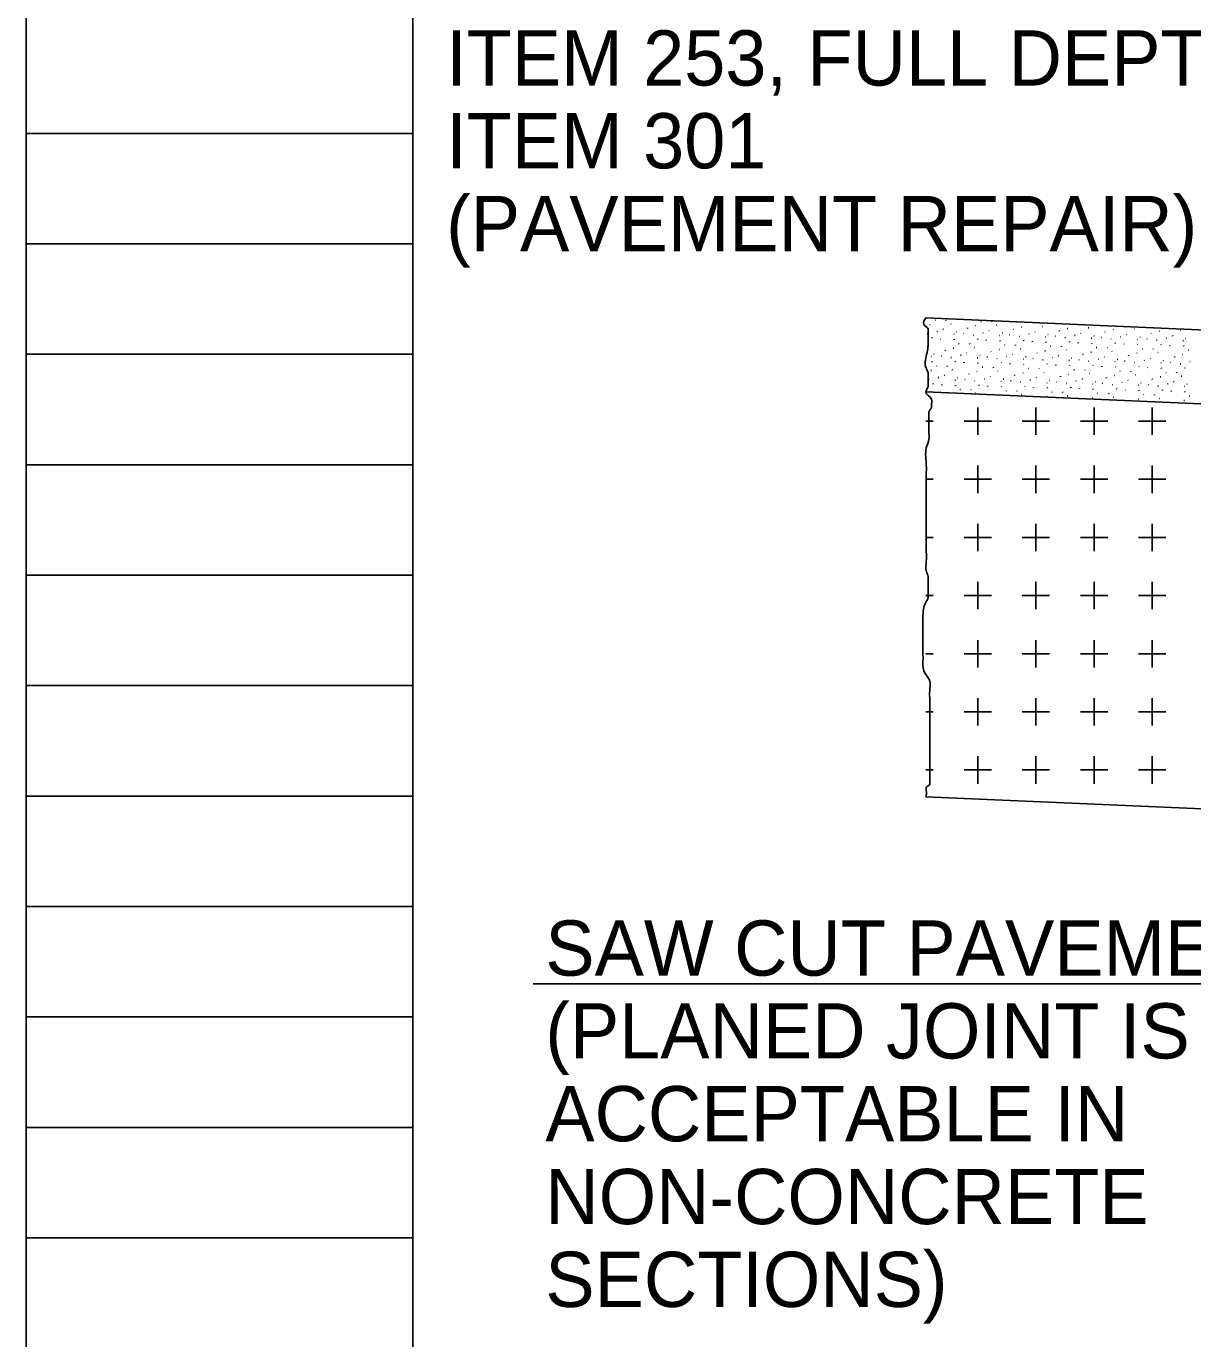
# Model space of a CAD drawing. Extents: x 0 to 34, y 0 to 22.
# Drawn here: x 16.76 to 19.716, y 10.524 to 13.852 of the extents above; entities that cross this region are included whole.
import ezdxf

# ---------------------------------------------------------------- set-up
doc = ezdxf.new("R2010")
doc.units = 0
doc.layers.add('Default', color=7, linetype='Continuous')
doc.layers.add('SH_Data', color=7, linetype='Continuous')

msp = doc.modelspace()

# ---------------------------------------------------------------- linework, layer by layer
at = {"layer": 'Default'}
for p, q in [((19.0496, 13.0955), (19.0506, 13.0951)), ((19.0633, 13.1068), (19.0645, 13.1066)), ((19.0681, 13.0776), (19.0691, 13.0775)), ((19.0833, 13.0835), (19.0845, 13.0826)), ((19.0915, 13.1056), (19.0908, 13.107)), ((19.1028, 13.0973), (19.104, 13.0971)), ((19.1458, 13.0856), (19.1453, 13.0871)), ((19.1658, 13.0921), (19.1668, 13.092)), ((19.1796, 13.1036), (19.1806, 13.1035)), ((19.1996, 13.0803), (19.2006, 13.0795)), ((19.2078, 13.1023), (19.2071, 13.1038)), ((19.2191, 13.094), (19.2201, 13.0938)), ((19.262, 13.0825), (19.2615, 13.0838)), ((19.2821, 13.089), (19.2831, 13.0886)), ((19.2958, 13.1003), (19.2968, 13.1001)), ((19.324, 13.0991), (19.3236, 13.1)), ((19.3353, 13.0908), (19.3365, 13.0906)), ((19.3783, 13.0791), (19.3778, 13.0806)), ((19.3983, 13.0856), (19.3995, 13.0855)), ((19.4516, 13.0875), (19.4526, 13.0873)), ((19.5146, 13.0825), (19.5156, 13.0821)), ((19.568, 13.0843), (19.569, 13.0841)), ((19.6308, 13.0791), (19.632, 13.079)), ((19.6841, 13.081), (19.6851, 13.0808)), ((19.0436, 13.0721), (19.0446, 13.0718)), ((19.0555, 13.0608), (19.0548, 13.0623)), ((19.0775, 13.0583), (19.077, 13.0596)), ((19.1105, 13.071), (19.1115, 13.0708)), ((19.112, 13.0568), (19.1115, 13.0581)), ((19.1166, 13.0768), (19.1178, 13.0765)), ((19.123, 13.0471), (19.1241, 13.0468)), ((19.1351, 13.0726), (19.1363, 13.0723)), ((19.1511, 13.0458), (19.1506, 13.0473)), ((19.1598, 13.0688), (19.161, 13.0686)), ((19.1718, 13.0576), (19.1711, 13.059)), ((19.1843, 13.0745), (19.1855, 13.0743)), ((19.1936, 13.055), (19.1931, 13.0563)), ((19.2266, 13.0676), (19.2278, 13.0675)), ((19.2283, 13.0535), (19.2278, 13.055)), ((19.233, 13.0735), (19.234, 13.0733)), ((19.2515, 13.0693), (19.2525, 13.0691)), ((19.2761, 13.0655), (19.2771, 13.0653)), ((19.288, 13.0543), (19.2875, 13.0558)), ((19.3006, 13.0711), (19.3016, 13.071)), ((19.31, 13.0518), (19.3093, 13.0531)), ((19.316, 13.077), (19.317, 13.0761)), ((19.343, 13.0643), (19.344, 13.0641)), ((19.3445, 13.0503), (19.344, 13.0516)), ((19.3491, 13.0703), (19.3503, 13.07)), ((19.3676, 13.066), (19.3686, 13.0658)), ((19.3925, 13.0623), (19.3935, 13.062)), ((19.4041, 13.0511), (19.4036, 13.0525)), ((19.4168, 13.068), (19.418, 13.0678)), ((19.4263, 13.0485), (19.4256, 13.0498)), ((19.4321, 13.0738), (19.4331, 13.073)), ((19.4591, 13.0611), (19.4603, 13.061)), ((19.4608, 13.047), (19.4603, 13.0485)), ((19.4655, 13.067), (19.4666, 13.0668)), ((19.484, 13.0628), (19.485, 13.0625)), ((19.4946, 13.076), (19.4941, 13.0773)), ((19.5086, 13.059), (19.5096, 13.0588)), ((19.5205, 13.0478), (19.52, 13.0493)), ((19.5331, 13.0646), (19.5343, 13.0645)), ((19.5425, 13.0453), (19.542, 13.0466)), ((19.5485, 13.0705), (19.5495, 13.0696)), ((19.5755, 13.0578), (19.5765, 13.0576)), ((19.5771, 13.0438), (19.5765, 13.0451)), ((19.5818, 13.0636), (19.5828, 13.0635)), ((19.6001, 13.0595), (19.6011, 13.0593)), ((19.6108, 13.0726), (19.6103, 13.074)), ((19.6248, 13.0558), (19.626, 13.0555)), ((19.6366, 13.0446), (19.6361, 13.046)), ((19.6495, 13.0613), (19.6505, 13.0611)), ((19.6646, 13.0673), (19.6656, 13.0663)), ((19.6916, 13.0546), (19.6928, 13.0545)), ((19.698, 13.0605), (19.699, 13.0601)), ((19.0463, 13.0408), (19.0473, 13.0406)), ((19.0538, 13.0145), (19.055, 13.0143)), ((19.0601, 13.0203), (19.0613, 13.02)), ((19.0786, 13.016), (19.0796, 13.0158)), ((19.0893, 13.0291), (19.0888, 13.0306)), ((19.1035, 13.0123), (19.1045, 13.0121)), ((19.1093, 13.0356), (19.1105, 13.0355)), ((19.1278, 13.018), (19.129, 13.0176)), ((19.1431, 13.0236), (19.1441, 13.0228)), ((19.1626, 13.0376), (19.1636, 13.0373)), ((19.1701, 13.0111), (19.1713, 13.011)), ((19.1765, 13.017), (19.1775, 13.0168)), ((19.1948, 13.0128), (19.196, 13.0126)), ((19.2055, 13.026), (19.205, 13.0273)), ((19.2256, 13.0325), (19.2266, 13.0323)), ((19.2393, 13.0438), (19.2403, 13.0436)), ((19.2441, 13.0146), (19.2453, 13.0145)), ((19.2593, 13.0205), (19.2605, 13.0196)), ((19.2675, 13.0426), (19.267, 13.044)), ((19.2788, 13.0343), (19.28, 13.0341)), ((19.2928, 13.0138), (19.2938, 13.0135)), ((19.3218, 13.0226), (19.3213, 13.024)), ((19.3418, 13.0291), (19.343, 13.029)), ((19.3556, 13.0406), (19.3566, 13.0403)), ((19.3605, 13.0115), (19.3615, 13.0111)), ((19.3756, 13.0171), (19.3766, 13.0163)), ((19.3836, 13.0393), (19.3831, 13.0408)), ((19.3951, 13.0311), (19.3961, 13.0308)), ((19.4381, 13.0195), (19.4375, 13.0208)), ((19.4581, 13.0258), (19.4593, 13.0256)), ((19.4718, 13.0373), (19.473, 13.0371)), ((19.4918, 13.014), (19.493, 13.0131)), ((19.5, 13.0361), (19.4995, 13.0375)), ((19.5113, 13.0278), (19.5125, 13.0275)), ((19.5543, 13.0161), (19.5538, 13.0175)), ((19.5745, 13.0226), (19.5755, 13.0225)), ((19.5881, 13.0341), (19.5891, 13.0338)), ((19.6163, 13.0328), (19.6156, 13.0343)), ((19.6276, 13.0245), (19.6286, 13.0243)), ((19.6586, 13.042), (19.6581, 13.0433)), ((19.6705, 13.013), (19.67, 13.0143)), ((19.6906, 13.0193), (19.6916, 13.0191)), ((19.6933, 13.0405), (19.6928, 13.042)), ((19.7043, 13.0308), (19.7053, 13.0306)), ((19.0528, 12.9791), (19.054, 12.979)), ((19.0555, 13.0003), (19.055, 13.0016)), ((19.0666, 12.9905), (19.0676, 12.9903)), ((19.0946, 12.9893), (19.0941, 12.9906)), ((19.1061, 12.9811), (19.1071, 12.9808)), ((19.1151, 13.0011), (19.1146, 13.0025)), ((19.1373, 12.9985), (19.1366, 13)), ((19.1718, 12.9971), (19.1713, 12.9985)), ((19.1828, 12.9873), (19.184, 12.9871)), ((19.211, 12.9861), (19.2105, 12.9875)), ((19.2196, 13.009), (19.2206, 13.0088)), ((19.2223, 12.9778), (19.2235, 12.9776)), ((19.2315, 12.998), (19.231, 12.9993)), ((19.2535, 12.9953), (19.253, 12.9966)), ((19.2865, 13.008), (19.2875, 13.0078)), ((19.288, 12.9938), (19.2875, 12.9951)), ((19.2991, 12.984), (19.3001, 12.9838)), ((19.3111, 13.0095), (19.3121, 13.0093)), ((19.3273, 12.9828), (19.3266, 12.9841)), ((19.3358, 13.0058), (19.337, 13.0056)), ((19.3476, 12.9946), (19.3471, 12.996)), ((19.3696, 12.992), (19.3691, 12.9933)), ((19.4026, 13.0046), (19.4038, 13.0045)), ((19.4043, 12.9905), (19.4038, 12.9918)), ((19.409, 13.0105), (19.41, 13.0103)), ((19.4153, 12.9808), (19.4163, 12.9806)), ((19.4275, 13.0063), (19.4285, 13.0061)), ((19.4435, 12.9796), (19.443, 12.981)), ((19.4521, 13.0025), (19.4531, 13.0023)), ((19.464, 12.9913), (19.4635, 12.9926)), ((19.4766, 13.0081), (19.4776, 13.008)), ((19.486, 12.9886), (19.4855, 12.9901)), ((19.519, 13.0015), (19.52, 13.0011)), ((19.5205, 12.9873), (19.52, 12.9886)), ((19.5251, 13.0073), (19.5263, 13.007)), ((19.5436, 13.003), (19.5448, 13.0028)), ((19.5685, 12.9993), (19.5695, 12.9991)), ((19.5803, 12.9881), (19.5796, 12.9895)), ((19.593, 13.005), (19.594, 13.0046)), ((19.6023, 12.9855), (19.6016, 12.9868)), ((19.6081, 13.0106), (19.6093, 13.0098)), ((19.6351, 12.9981), (19.6363, 12.998)), ((19.6368, 12.984), (19.6363, 12.9853)), ((19.6415, 13.004), (19.6426, 13.0038)), ((19.66, 12.9998), (19.661, 12.9996)), ((19.6846, 12.996), (19.6858, 12.9958)), ((19.6965, 12.9848), (19.696, 12.9861)), ((19.7091, 13.0016), (19.7101, 13.0015)), ((19.0468, 12.9558), (19.048, 12.9555)), ((19.0586, 12.9446), (19.0581, 12.946)), ((19.0715, 12.9615), (19.0725, 12.9613)), ((19.0866, 12.9673), (19.0876, 12.9665)), ((19.1136, 12.9546), (19.1148, 12.9545)), ((19.12, 12.9605), (19.121, 12.9603)), ((19.1385, 12.9563), (19.1395, 12.956)), ((19.149, 12.9695), (19.1485, 12.9708)), ((19.1631, 12.9525), (19.1641, 12.9523)), ((19.1691, 12.976), (19.1703, 12.9756)), ((19.1876, 12.9581), (19.1886, 12.958)), ((19.2028, 12.964), (19.204, 12.9631)), ((19.23, 12.9515), (19.231, 12.9511)), ((19.2361, 12.9571), (19.2373, 12.957)), ((19.2546, 12.953), (19.2558, 12.9528)), ((19.2653, 12.9661), (19.2648, 12.9676)), ((19.2795, 12.9493), (19.2805, 12.949)), ((19.2855, 12.9726), (19.2865, 12.9725)), ((19.3038, 12.955), (19.305, 12.9546)), ((19.3191, 12.9608), (19.3203, 12.96)), ((19.3386, 12.9745), (19.3396, 12.9743)), ((19.3461, 12.9481), (19.3471, 12.948)), ((19.3525, 12.954), (19.3536, 12.9538)), ((19.371, 12.9498), (19.372, 12.9495)), ((19.3815, 12.963), (19.381, 12.9643)), ((19.3956, 12.946), (19.3966, 12.9458)), ((19.4016, 12.9695), (19.4026, 12.9691)), ((19.4201, 12.9516), (19.4211, 12.9515)), ((19.4355, 12.9575), (19.4365, 12.9566)), ((19.4548, 12.9713), (19.4558, 12.9711)), ((19.4625, 12.945), (19.4635, 12.9446)), ((19.4688, 12.9506), (19.4698, 12.9505)), ((19.4871, 12.9465), (19.4881, 12.9463)), ((19.4978, 12.9596), (19.4973, 12.9611)), ((19.5178, 12.9661), (19.519, 12.966)), ((19.5316, 12.9775), (19.5326, 12.9773)), ((19.5365, 12.9485), (19.5375, 12.9481)), ((19.5516, 12.9541), (19.5526, 12.9533)), ((19.5596, 12.9763), (19.5591, 12.9776)), ((19.5711, 12.968), (19.5721, 12.9678)), ((19.585, 12.9475), (19.586, 12.9473)), ((19.6141, 12.9563), (19.6136, 12.9578)), ((19.6341, 12.963), (19.6351, 12.9626)), ((19.6478, 12.9743), (19.649, 12.9741)), ((19.6526, 12.9451), (19.6538, 12.945)), ((19.6678, 12.951), (19.669, 12.9501)), ((19.676, 12.9731), (19.6755, 12.9745)), ((19.6873, 12.9648), (19.6885, 12.9646)), ((19.0496, 12.9246), (19.0506, 12.9245)), ((19.0806, 12.942), (19.0801, 12.9433)), ((19.1153, 12.9405), (19.1148, 12.942)), ((19.1263, 12.9308), (19.1273, 12.9306)), ((19.1545, 12.9296), (19.154, 12.931)), ((19.1658, 12.9213), (19.1668, 12.9211)), ((19.175, 12.9413), (19.1745, 12.9428)), ((19.197, 12.9388), (19.1965, 12.9401)), ((19.2315, 12.9373), (19.231, 12.9386)), ((19.2426, 12.9276), (19.2436, 12.9273)), ((19.2706, 12.9263), (19.2701, 12.9278)), ((19.2821, 12.918), (19.2831, 12.9178)), ((19.2913, 12.9381), (19.2906, 12.9395)), ((19.3131, 12.9355), (19.3126, 12.9368)), ((19.3451, 12.9128), (19.3461, 12.9126)), ((19.3478, 12.934), (19.3473, 12.9355)), ((19.3588, 12.9243), (19.36, 12.9241)), ((19.387, 12.9231), (19.3865, 12.9245)), ((19.3983, 12.9148), (19.3995, 12.9145)), ((19.4075, 12.9348), (19.407, 12.9363)), ((19.4295, 12.9323), (19.429, 12.9336)), ((19.4641, 12.9308), (19.4635, 12.9321)), ((19.4751, 12.921), (19.4761, 12.9208)), ((19.5033, 12.9198), (19.5028, 12.9211)), ((19.512, 12.9428), (19.513, 12.9425)), ((19.5146, 12.9115), (19.5156, 12.9113)), ((19.5236, 12.9316), (19.5231, 12.933)), ((19.5458, 12.929), (19.5451, 12.9303)), ((19.5786, 12.9416), (19.5798, 12.9415)), ((19.5803, 12.9275), (19.5798, 12.929)), ((19.5913, 12.9178), (19.5925, 12.9175)), ((19.6035, 12.9433), (19.6045, 12.943)), ((19.6195, 12.9165), (19.619, 12.918)), ((19.6281, 12.9395), (19.6291, 12.9393)), ((19.64, 12.9283), (19.6395, 12.9298)), ((19.662, 12.9258), (19.6615, 12.9271)), ((19.695, 12.9385), (19.696, 12.9381)), ((19.6965, 12.9243), (19.696, 12.9256)), ((19.7013, 12.9441), (19.7023, 12.944)), ((19.7076, 12.9145), (19.7086, 12.9143)), ((19.1715, 12.8158), (19.1715, 12.8853)), ((19.3188, 12.8506), (19.3188, 12.8853)), ((19.4615, 12.9096), (19.4625, 12.9095)), ((19.4663, 12.8158), (19.4663, 12.8853)), ((19.5776, 12.9063), (19.5788, 12.9061)), ((19.6136, 12.8506), (19.6136, 12.8853)), ((19.6308, 12.9083), (19.632, 12.908)), ((19.6736, 12.897), (19.6733, 12.898)), ((19.694, 12.9031), (19.695, 12.903)), ((19.04, 12.8506), (19.0586, 12.8506)), ((19.1366, 12.8506), (19.2061, 12.8506)), ((19.2841, 12.8506), (19.3188, 12.8506)), ((19.3188, 12.8158), (19.3188, 12.8506)), ((19.3188, 12.8506), (19.3536, 12.8506)), ((19.4315, 12.8506), (19.501, 12.8506)), ((19.579, 12.8506), (19.6136, 12.8506)), ((19.6136, 12.8158), (19.6136, 12.8506)), ((19.6136, 12.8506), (19.6485, 12.8506)), ((19.1715, 12.7031), (19.1715, 12.7378)), ((19.3188, 12.6683), (19.3188, 12.7378)), ((19.4663, 12.7031), (19.4663, 12.7378)), ((19.6136, 12.6683), (19.6136, 12.7378)), ((19.04, 12.7031), (19.0586, 12.7031)), ((19.1366, 12.7031), (19.1715, 12.7031)), ((19.1715, 12.6683), (19.1715, 12.7031)), ((19.1715, 12.7031), (19.2061, 12.7031)), ((19.2841, 12.7031), (19.3536, 12.7031)), ((19.4315, 12.7031), (19.4663, 12.7031)), ((19.4663, 12.6683), (19.4663, 12.7031)), ((19.4663, 12.7031), (19.501, 12.7031)), ((19.579, 12.7031), (19.6485, 12.7031)), ((19.1715, 12.521), (19.1715, 12.5905)), ((19.3188, 12.5556), (19.3188, 12.5905)), ((19.4663, 12.521), (19.4663, 12.5905)), ((19.6136, 12.5556), (19.6136, 12.5905)), ((19.04, 12.5556), (19.0586, 12.5556)), ((19.1366, 12.5556), (19.2061, 12.5556)), ((19.2841, 12.5556), (19.3188, 12.5556)), ((19.3188, 12.521), (19.3188, 12.5556)), ((19.3188, 12.5556), (19.3536, 12.5556)), ((19.4315, 12.5556), (19.501, 12.5556)), ((19.579, 12.5556), (19.6136, 12.5556)), ((19.6136, 12.521), (19.6136, 12.5556)), ((19.6136, 12.5556), (19.6485, 12.5556)), ((19.1715, 12.4083), (19.1715, 12.443)), ((19.3188, 12.3735), (19.3188, 12.443)), ((19.4663, 12.4083), (19.4663, 12.443)), ((19.6136, 12.3735), (19.6136, 12.443)), ((19.04, 12.4083), (19.0586, 12.4083)), ((19.1366, 12.4083), (19.1715, 12.4083)), ((19.1715, 12.3735), (19.1715, 12.4083)), ((19.1715, 12.4083), (19.2061, 12.4083)), ((19.2841, 12.4083), (19.3536, 12.4083)), ((19.4315, 12.4083), (19.4663, 12.4083)), ((19.4663, 12.3735), (19.4663, 12.4083)), ((19.4663, 12.4083), (19.501, 12.4083)), ((19.579, 12.4083), (19.6485, 12.4083)), ((19.1715, 12.2261), (19.1715, 12.2956)), ((19.3188, 12.2608), (19.3188, 12.2956)), ((19.4663, 12.2261), (19.4663, 12.2956)), ((19.6136, 12.2608), (19.6136, 12.2956)), ((19.04, 12.2608), (19.0586, 12.2608)), ((19.1366, 12.2608), (19.2061, 12.2608)), ((19.2841, 12.2608), (19.3188, 12.2608)), ((19.3188, 12.2261), (19.3188, 12.2608)), ((19.3188, 12.2608), (19.3536, 12.2608)), ((19.4315, 12.2608), (19.501, 12.2608)), ((19.579, 12.2608), (19.6136, 12.2608)), ((19.6136, 12.2261), (19.6136, 12.2608)), ((19.6136, 12.2608), (19.6485, 12.2608)), ((19.1715, 12.1135), (19.1715, 12.1483)), ((19.3188, 12.0788), (19.3188, 12.1483)), ((19.4663, 12.1135), (19.4663, 12.1483)), ((19.6136, 12.0788), (19.6136, 12.1483)), ((19.04, 12.1135), (19.0586, 12.1135)), ((19.1366, 12.1135), (19.1715, 12.1135)), ((19.1715, 12.0788), (19.1715, 12.1135)), ((19.1715, 12.1135), (19.2061, 12.1135)), ((19.2841, 12.1135), (19.3536, 12.1135)), ((19.4315, 12.1135), (19.4663, 12.1135)), ((19.4663, 12.0788), (19.4663, 12.1135)), ((19.4663, 12.1135), (19.501, 12.1135)), ((19.579, 12.1135), (19.6485, 12.1135)), ((19.1715, 11.9313), (19.1715, 12.0008)), ((19.3188, 11.9661), (19.3188, 12.0008)), ((19.4663, 11.9313), (19.4663, 12.0008)), ((19.6136, 11.9661), (19.6136, 12.0008)), ((19.04, 11.9661), (19.0586, 11.9661)), ((19.1366, 11.9661), (19.2061, 11.9661)), ((19.2841, 11.9661), (19.3188, 11.9661)), ((19.3188, 11.9313), (19.3188, 11.9661)), ((19.3188, 11.9661), (19.3536, 11.9661)), ((19.4315, 11.9661), (19.501, 11.9661)), ((19.579, 11.9661), (19.6136, 11.9661)), ((19.6136, 11.9313), (19.6136, 11.9661)), ((19.6136, 11.9661), (19.6485, 11.9661)), ((18.0449, 11.4239), (20.415, 11.4239))]:
    msp.add_line(p, q, dxfattribs=at)
for points in [[(19.04, 13.1123), (20.0011, 13.0706)], [(19.04, 12.9245), (21.0142, 12.8389)], [(19.04, 11.8978), (21.394, 11.7958), (21.4015, 11.7948)]]:
    msp.add_lwpolyline(points, dxfattribs=at)
msp.add_spline([(19.04, 13.1123), (19.0346, 13.0963), (19.0455, 13.0843), (19.0455, 13.0721), (19.0455, 13.0681), (19.0455, 13.056), (19.0455, 13.0438), (19.039, 13.0053), (19.039, 12.9891), (19.0455, 12.973), (19.0455, 12.9648), (19.0455, 12.9608), (19.0455, 12.9526), (19.0455, 12.9425), (19.0455, 12.9385), (19.04, 12.9245), (19.0541, 12.9061), (19.0541, 12.89), (19.0541, 12.8858), (19.0476, 12.8736), (19.0476, 12.8656), (19.0476, 12.8535), (19.0476, 12.8353), (19.0476, 12.8231), (19.0476, 12.8048), (19.0411, 12.7826), (19.0411, 12.738), (19.0411, 12.7218), (19.0411, 12.6895), (19.0411, 12.6611), (19.0411, 12.6388), (19.0411, 12.6266), (19.0411, 12.6005), (19.0411, 12.5963), (19.0411, 12.5841), (19.0411, 12.568), (19.0411, 12.5498), (19.0411, 12.5416), (19.0411, 12.5193), (19.0411, 12.4951), (19.0411, 12.4708), (19.0455, 12.4566), (19.0455, 12.4485), (19.0455, 12.4405), (19.0455, 12.4201), (19.0455, 12.412), (19.0455, 12.404), (19.039, 12.3898), (19.0326, 12.3575), (19.0326, 12.3493), (19.0326, 12.3311), (19.0326, 12.323), (19.0326, 12.3108), (19.0326, 12.2926), (19.0326, 12.2805), (19.0326, 12.2623), (19.0326, 12.242), (19.0326, 12.2298), (19.0368, 12.2136), (19.0498, 12.1913), (19.0498, 12.1671), (19.0498, 12.1428), (19.0498, 12.1225), (19.0498, 12.0861), (19.0498, 12.0496), (19.0498, 12.0275), (19.0498, 12.0011), (19.0498, 11.9828), (19.0498, 11.9646), (19.0498, 11.9606), (19.0498, 11.9423), (19.0498, 11.9383), (19.0498, 11.9301), (19.0411, 11.9221), (19.0411, 11.914), (19.04, 11.8978)], degree=3, dxfattribs=at)
at = {"layer": 'SH_Data'}
for p, q in [((16.76, 0.98), (16.76, 21.14)), ((17.74, 0.98), (17.74, 21.14)), ((16.76, 13.58), (17.74, 13.58)), ((16.76, 13.3), (17.74, 13.3)), ((16.76, 13.02), (17.74, 13.02)), ((16.76, 12.74), (17.74, 12.74)), ((16.76, 12.46), (17.74, 12.46)), ((16.76, 12.18), (17.74, 12.18)), ((16.76, 11.9), (17.74, 11.9)), ((16.76, 11.62), (17.74, 11.62)), ((16.76, 11.34), (17.74, 11.34)), ((16.76, 11.06), (17.74, 11.06)), ((16.76, 10.78), (17.74, 10.78))]:
    msp.add_line(p, q, dxfattribs=at)

# ---------------------------------------------------------------- texts
at = {"layer": 'Default'}
for s, p in [('ITEM 253, FULL DEPTH OF 6"', (17.8242, 13.7014)), ('ITEM 301', (17.8242, 13.4914)), ('(PAVEMENT REPAIR)', (17.8242, 13.2814)), ('SAW CUT PAVEMENT', (18.0755, 11.4447)), ('(PLANED JOINT IS', (18.0755, 11.2347)), ('ACCEPTABLE IN', (18.0755, 11.0247)), ('NON-CONCRETE', (18.0755, 10.8147)), ('SECTIONS)', (18.0755, 10.6047))]:
    msp.add_text(s, height=0.14, dxfattribs=at).set_placement(p)

doc.saveas('drawing.dxf')
